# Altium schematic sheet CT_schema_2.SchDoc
size 360 x 214 mm
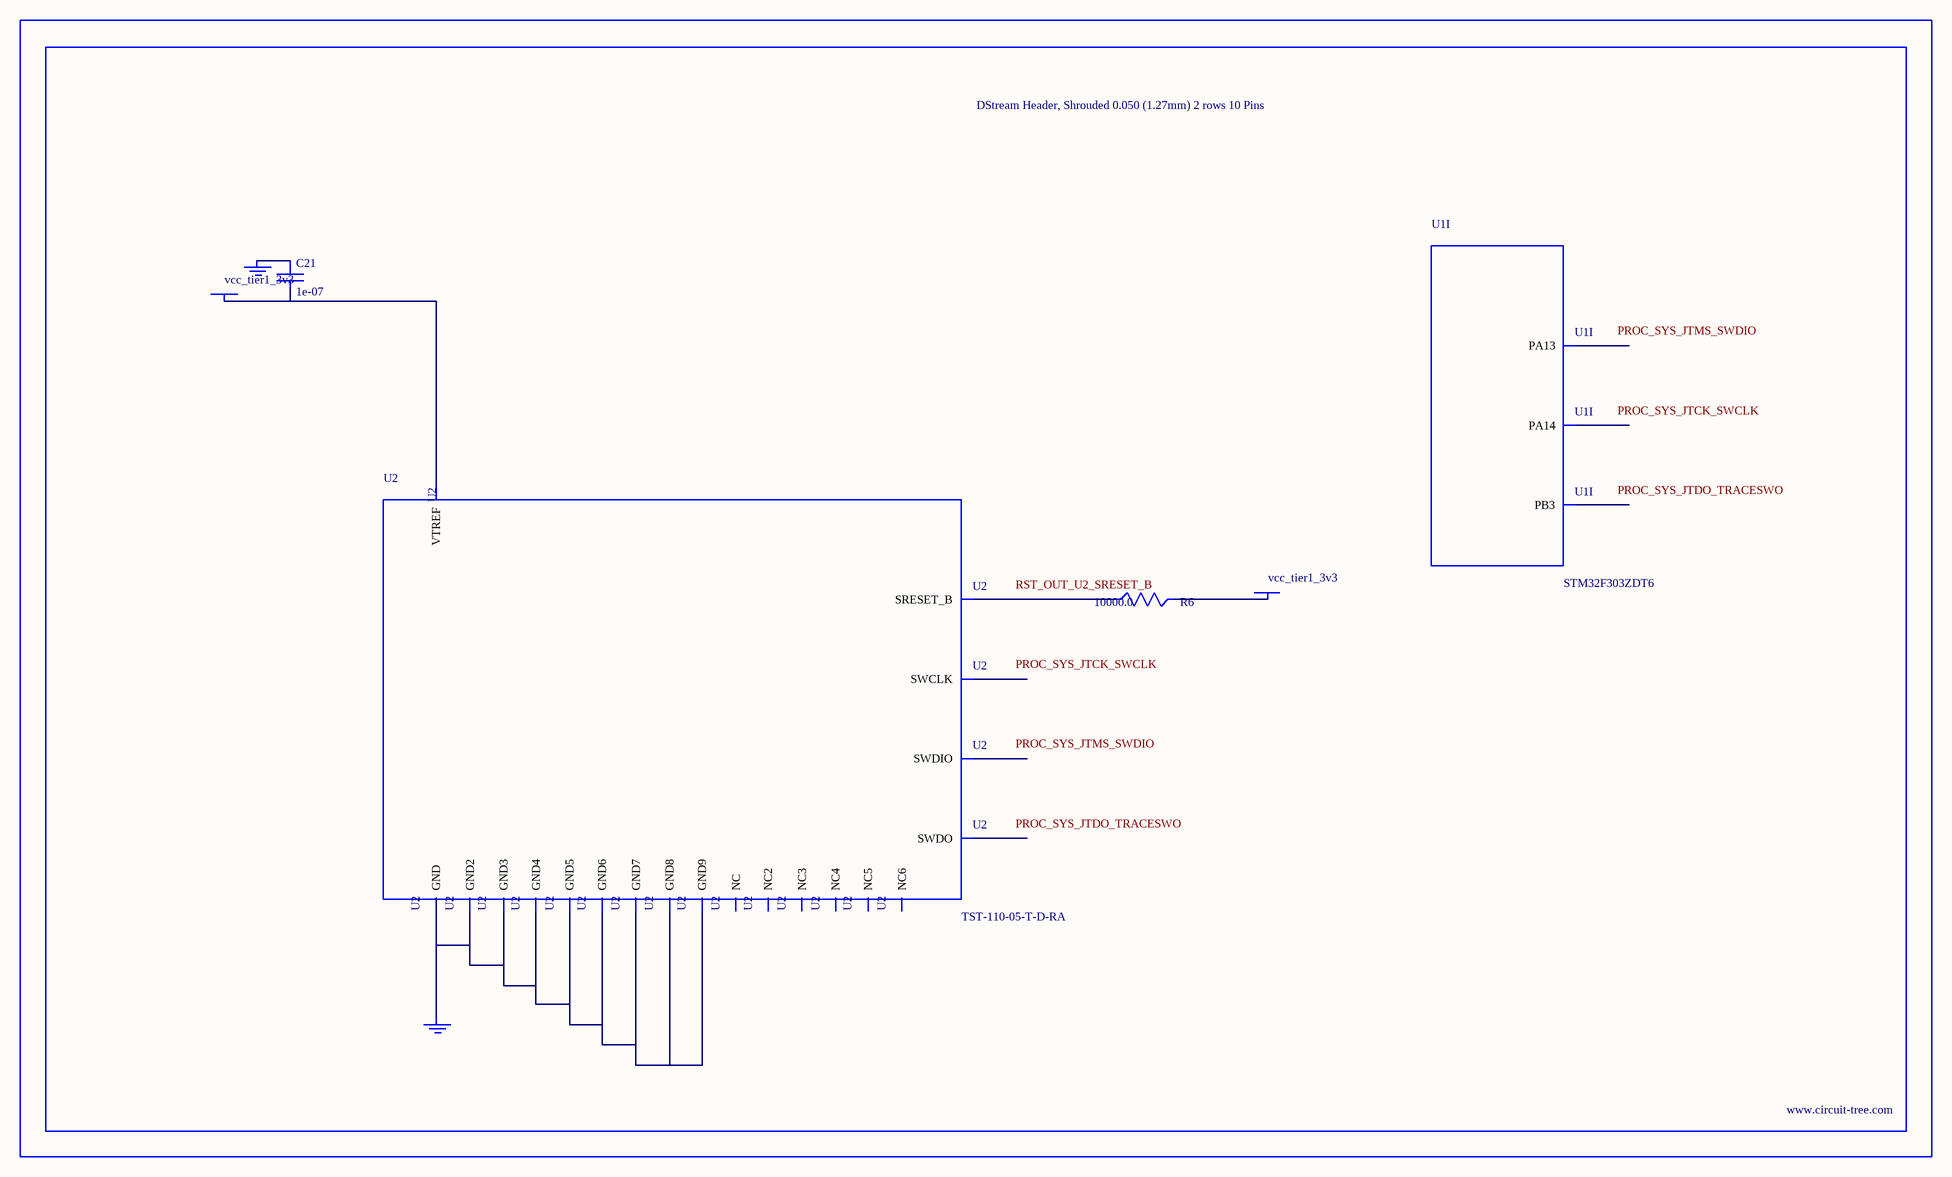
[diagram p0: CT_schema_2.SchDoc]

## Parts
BORDER1  (no value)
C21  1e-07  [C0402]
GND_INSTANCE_1_0  (no value)
GND_INSTANCE_1_1  (no value)
POWER_INSTANCE_1_0  vcc_tier1_3v3
POWER_INSTANCE_1_1  vcc_tier1_3v3
R6  10000.0  [R0603]
U1  STM32F303ZDT6  [LQFP144]  (part I of 13)
U2  TST-110-05-T-D-RA  [TST-110-05-T-D-RA]

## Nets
NetC21_1: C21.1 GND_INSTANCE_1_0.0(GND)
NetC21_2: C21.2 POWER_INSTANCE_1_0.0(PWR) U2.1(VTREF)
NetGND_INSTANCE_1_1_0: GND_INSTANCE_1_1.0(GND) U2.4(GND) U2.6(GND2) U2.8(GND3) U2.10(GND4) U2.12(GND5) U2.14(GND6) U2.16(GND7) U2.18(GND8) U2.20(GND9)
NetPOWER_INSTANCE_1_1_0: POWER_INSTANCE_1_1.0(PWR) R6.2
NetR6_1: R6.1 U2.15(SRESET_B)

Not connected (* = marked no-connect by the designer): U1 105(PA13) 109(PA14) 133(PB3); U2 2(NC) 3(NC2) 5(NC3) 7(SWDIO) 9(SWCLK) 11(NC4) 13(SWDO) 17(NC5) 19(NC6)

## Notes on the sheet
- Labels drawn without touching a wire or pin: PROC_SYS_JTCK_SWCLK, PROC_SYS_JTDO_TRACESWO, PROC_SYS_JTMS_SWDIO, RST_OUT_U2_SRESET_B

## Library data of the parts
BORDER1 = BORDER_PAGE1
C21 = C0402C104K3RACTU
GND_INSTANCE_1_0 GND_INSTANCE_1_1 = GND
POWER_INSTANCE_1_0 POWER_INSTANCE_1_1 = PWR
R6 = RC0603JR-0710KL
